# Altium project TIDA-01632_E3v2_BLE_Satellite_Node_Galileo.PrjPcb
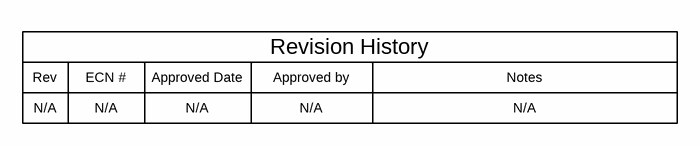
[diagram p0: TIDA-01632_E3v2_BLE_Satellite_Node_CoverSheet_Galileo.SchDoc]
CopyrightYear: 2017; PCB_Layout: Donovan Porter; PCB_Rev: E3; PRJ_Customer: Public Release; PRJ_Engineer: Donovan Porter; PRJ_Number: TIDA-01632; PRJ_Title: TIDA-01632 BLE Car Access Satellite Node Reference Design; SCH_Rev: E3; TechSupport: http://www.ti.com/support; TID: TIDA-01632
3 sheets, 78 parts. Net scope: global (net labels, ports and power ports of the same name join across sheets).
Board file: TIDA-01632_E3v2_BLE_Satellite_Node_Galileo.PcbDoc
Sheets:
  TIDA-01632_E3v2_BLE_Satellite_Node_CoverSheet_Galileo.SchDoc
  TIDA-01632_E3v2_BLE_Satellite_Node_Main_Galileo.SchDoc
  TIDA-01632_E3v2_BLE_Satellite_Node_Hardware_Galileo.SchDoc

## Sheet TIDA-01632_E3v2_BLE_Satellite_Node_CoverSheet_Galileo.SchDoc
size 431 x 279 mm; Date: Not shown in title block; ApprovedBy: Not shown in title block; CheckedBy: Not shown in title block; Author: Not shown in title block; CompanyName: Not shown in title block; Engineer: Not shown in title block; Organization: Not shown in title block; Address1: Not shown in title block; Address2: Not shown in title block; Address3: Not shown in title block; Address4: Not shown in title block; DocumentNumber: 1; Revision: Use project parameter SCH_Rev; SheetNumber: 1; SheetTotal: 3; PageSetup: Record=PageOptions¦CenterHorizontal=True¦CenterVertical=True¦PrintScale=1.00¦XCorrection=1.00¦YCorrection=1.00¦PrintKind=0¦BorderSize=5000000¦LeftOffset=0¦BottomOffset=0¦Orientation=2¦PaperLength=1000¦PaperWidth=1000¦Scale=100¦PaperSource=15¦PrintQuality=600¦MediaType=1¦DitherType=10¦PaperKind=Letter¦PrintScaleMode=1

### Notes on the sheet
- Rev
- N/A
- ECN #
- Approved Date
- Approved by
- Revision History
- Notes

## Sheet TIDA-01632_E3v2_BLE_Satellite_Node_Main_Galileo.SchDoc
size 431 x 279 mm; Date: Not shown in title block; ApprovedBy: Not shown in title block; CheckedBy: Not shown in title block; Author: Not shown in title block; CompanyName: Not shown in title block; Engineer: Not shown in title block; Organization: Not shown in title block; Address1: Not shown in title block; Address2: Not shown in title block; Address3: Not shown in title block; Address4: Not shown in title block; DocumentNumber: 2; Revision: Use project parameter SCH_Rev; SheetNumber: 2; SheetTotal: 3; PageSetup: Record=PageOptions¦CenterHorizontal=True¦CenterVertical=True¦PrintScale=1.00¦XCorrection=1.00¦YCorrection=1.00¦PrintKind=0¦BorderSize=5000000¦LeftOffset=0¦BottomOffset=0¦Orientation=2¦PaperLength=1000¦PaperWidth=1000¦Scale=100¦PaperSource=15¦PrintQuality=600¦MediaType=1¦DitherType=10¦PaperKind=Letter¦PrintScaleMode=1
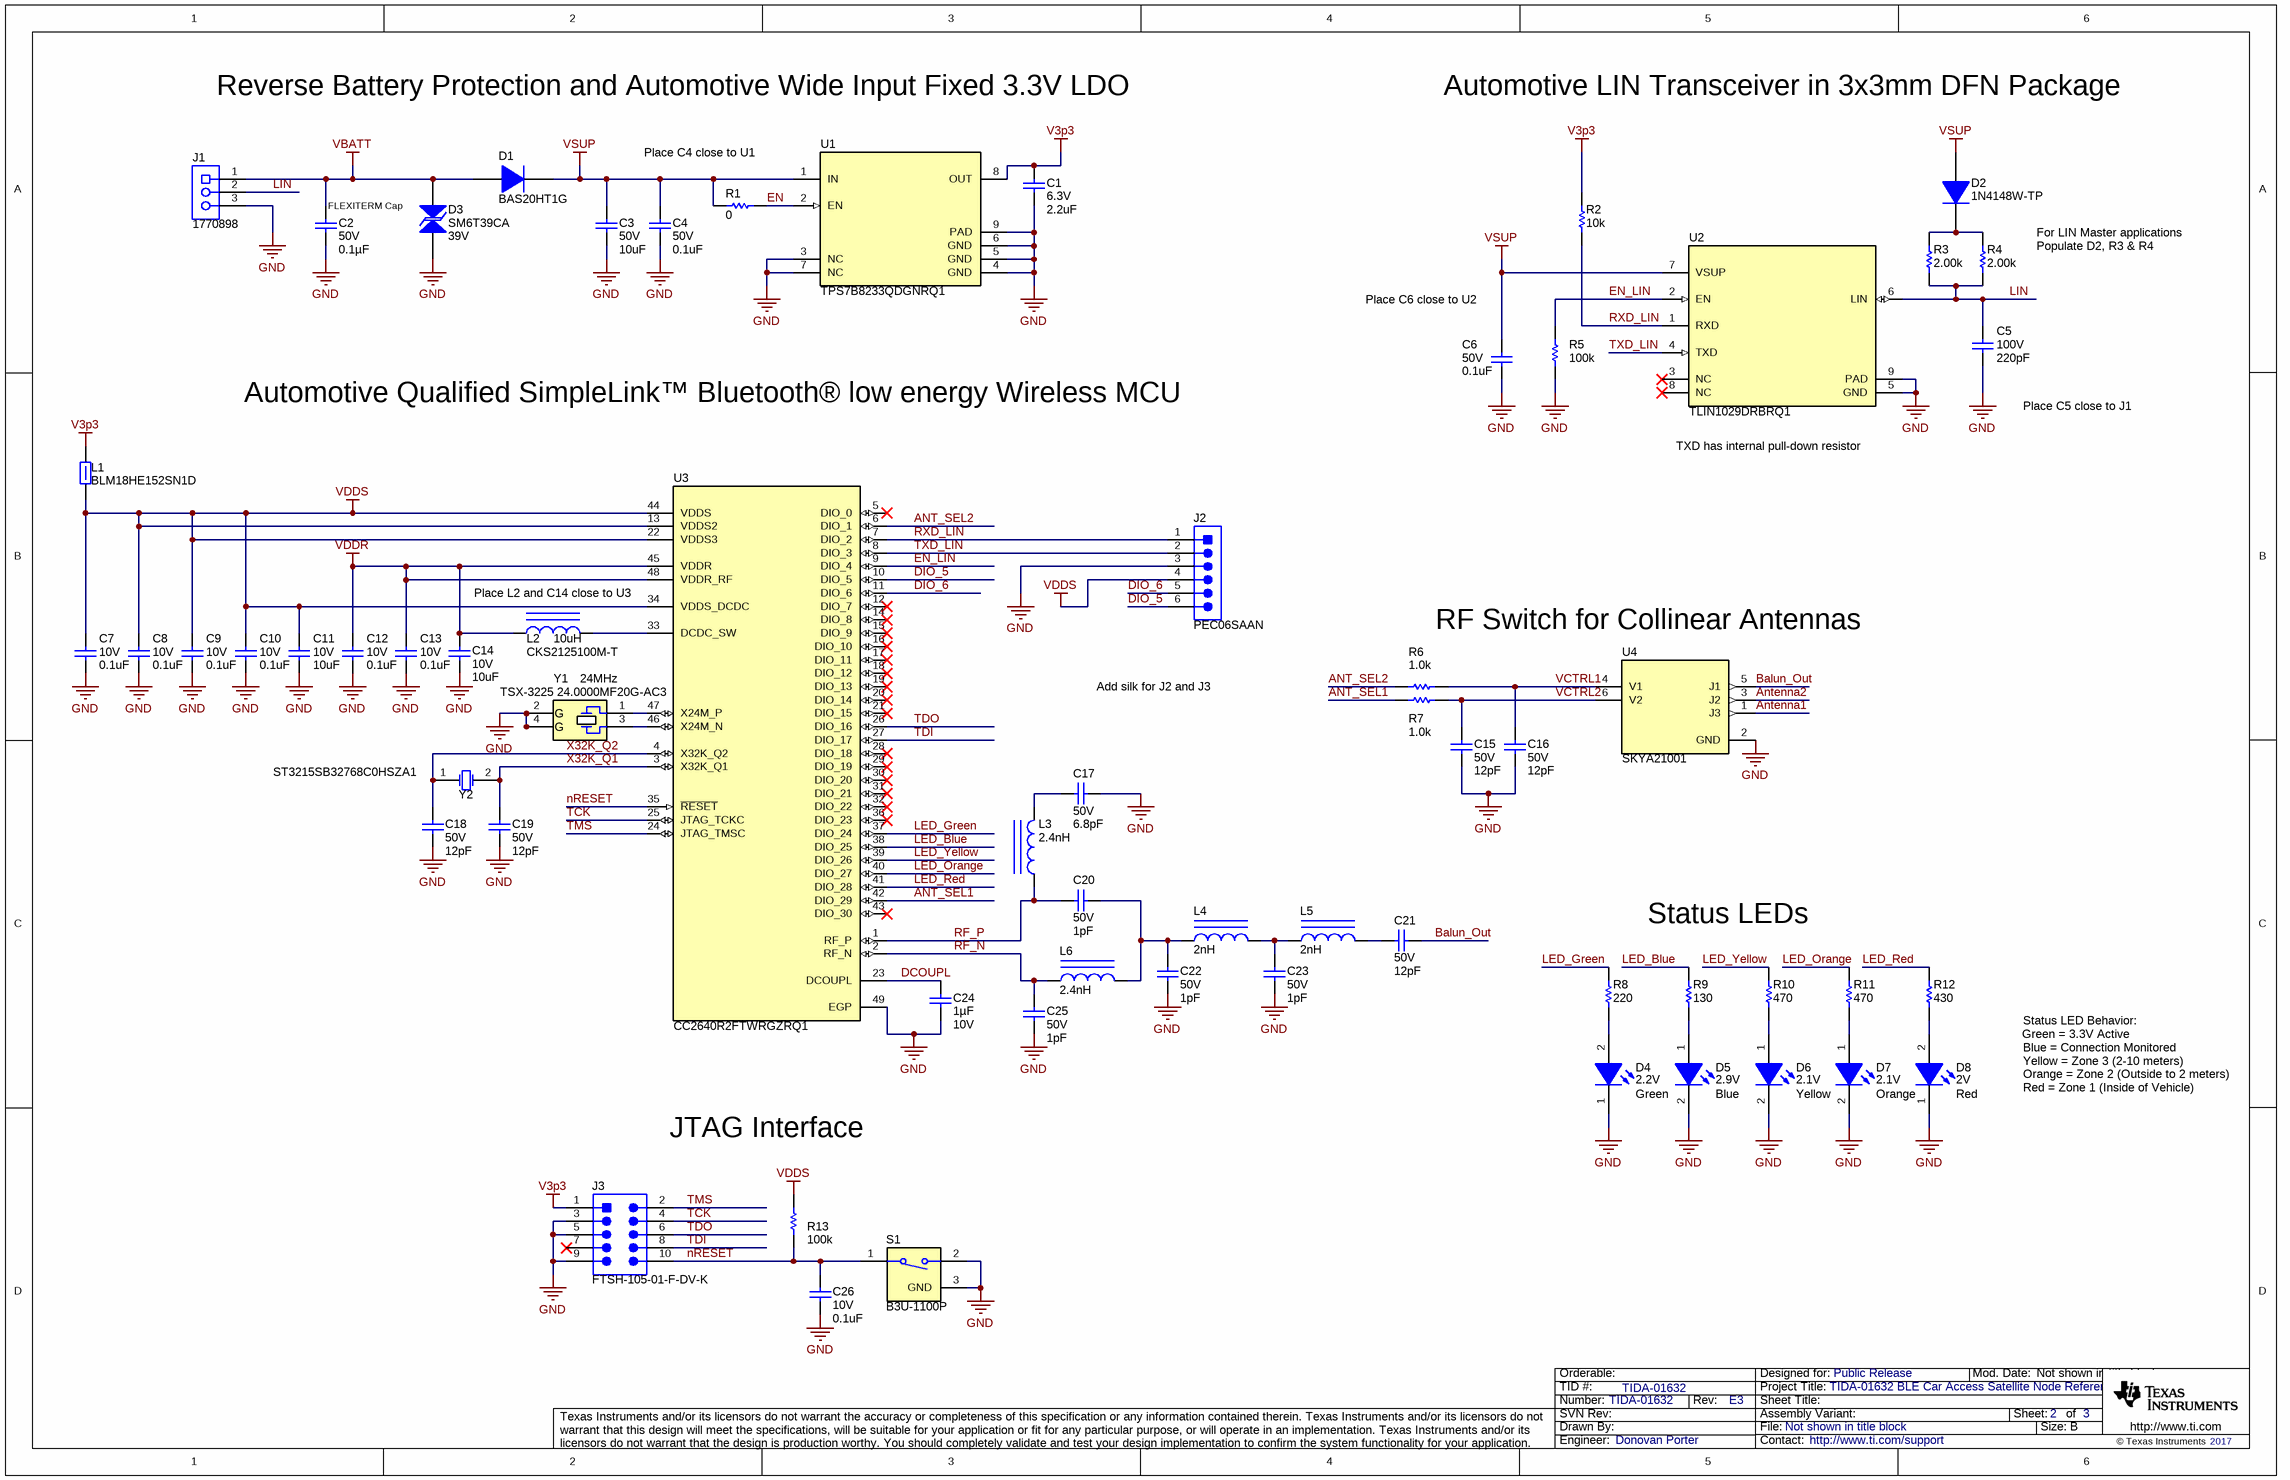
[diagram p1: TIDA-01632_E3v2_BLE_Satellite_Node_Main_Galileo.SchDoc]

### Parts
C1  VDC_V: 6.3V  ValueDisplayed: 2.2uF  [0603]  (hidden comment: GCM188R70J225KE22D)
C2  VDC_V: 50V  ValueDisplayed: 0.1µF  [0603]  (hidden comment: 06035C104KAZ2A)
C3  VDC_V: 50V  ValueDisplayed: 10uF  [1210_280]  (hidden comment: UMK325AB7106KMHT)
C4  VDC_V: 50V  ValueDisplayed: 0.1uF  [0402]  (hidden comment: GCM155R71H104KE02D)
C5  VDC_V: 100V  ValueDisplayed: 220pF  [0402]  (hidden comment: GRM155R72A221KA01D)
C6  VDC_V: 50V  ValueDisplayed: 0.1uF  [0402]  (hidden comment: GCM155R71H104KE02D)
C7  VDC_V: 10V  ValueDisplayed: 0.1uF  [0402L]  (hidden comment: CL05B104KP5NNNC)
C8  VDC_V: 10V  ValueDisplayed: 0.1uF  [0402]  (hidden comment: CL05B104KP5NNNC)
C9  VDC_V: 10V  ValueDisplayed: 0.1uF  [0402]  (hidden comment: CL05B104KP5NNNC)
C10  VDC_V: 10V  ValueDisplayed: 0.1uF  [0402]  (hidden comment: CL05B104KP5NNNC)
C11  VDC_V: 10V  ValueDisplayed: 10uF  [0603]  (hidden comment: GRM188Z71A106MA73D)
C12  VDC_V: 10V  ValueDisplayed: 0.1uF  [0402L]  (hidden comment: CL05B104KP5NNNC)
C13  VDC_V: 10V  ValueDisplayed: 0.1uF  [0402L]  (hidden comment: CL05B104KP5NNNC)
C14  VDC_V: 10V  ValueDisplayed: 10uF  [0603]  (hidden comment: GRM188Z71A106MA73D)
C15  VDC_V: 50V  ValueDisplayed: 12pF  [0402L]  (hidden comment: GRM1555C1H120JA01D)
C16  VDC_V: 50V  ValueDisplayed: 12pF  [0402L]  (hidden comment: GRM1555C1H120JA01D)
C17  VDC_V: 50V  ValueDisplayed: 6.8pF  [0402]  (hidden comment: GRM1555C1H6R8CA01D)
C18  VDC_V: 50V  ValueDisplayed: 12pF  [0402]  (hidden comment: GRM1555C1H120JA01D)
C19  VDC_V: 50V  ValueDisplayed: 12pF  [0402]  (hidden comment: GRM1555C1H120JA01D)
C20  VDC_V: 50V  ValueDisplayed: 1pF  [0402]  (hidden comment: GRM1555C1H1R0CA01D)
C21  VDC_V: 50V  ValueDisplayed: 12pF  [0402L]  (hidden comment: GRM1555C1H120JA01D)
C22  VDC_V: 50V  ValueDisplayed: 1pF  [0402]  (hidden comment: GRM1555C1H1R0CA01D)
C23  VDC_V: 50V  ValueDisplayed: 1pF  [0402L]  (hidden comment: GRM1555C1H1R0CA01D)
C24  Cap_F: 1µF  VDC_V: 10V  [0603L]  (hidden comment: GRM188R71A105KA61D)
C25  VDC_V: 50V  ValueDisplayed: 1pF  [0402]  (hidden comment: GRM1555C1H1R0CA01D)
C26  VDC_V: 10V  ValueDisplayed: 0.1uF  [0402]  (hidden comment: CL05B104KP5NNNC)
D1  BAS20HT1G  [SOD-323]
D2  1N4148W-TP  [SOD-123]
D3  SM6T39CA  value 39V  [SMB-Bi]
D4  value Green  Vf_V: 2.2V  [SML-P1_GREEN]  (hidden comment: SML-P12PTT86)
D5  value Blue  Vf_V: 2.9V  [LED_SMLP12_BLUE]  (hidden comment: SMLP12BC7TT86)
D6  value Yellow  Vf_V: 2.1V  [LED_SMLP12_YELLOW]  (hidden comment: SML-P12YTT86)
D7  value Orange  Vf_V: 2.1V  [LED_SMLP12_ORANGE]  (hidden comment: SML-P12DTT86)
D8  value Red  Vf_V: 2V  [SML-P1_RED]  (hidden comment: SML-P12VTT86)
J1  1770898  [Phoenix_1770898]
J2  PEC06SAAN  [Sullins_PEC06SAAN]
J3  FTSH-105-01-F-DV-K  [Samtec_FTSH-105-01-x-DV-K]
L1  BLM18HE152SN1D  [0603]
L2  ValueDisplayed: 10uH  [0805_HV]  (hidden comment: CKS2125100M-T)
L3  ValueDisplayed: 2.4nH  [IND_LQG15H]  (hidden comment: LQG15HS2N4S02D)
L4  ValueDisplayed: 2nH  [IND_LQG15H]  (hidden comment: LQG15HS2N0S02D)
L5  ValueDisplayed: 2nH  [IND_LQG15H]  (hidden comment: LQG15HS2N0S02D)
L6  ValueDisplayed: 2.4nH  [IND_LQG15H]  (hidden comment: LQG15HS2N4S02D)
R1  ValueDisplayed: 0  [0402]  (hidden comment: CRCW04020000Z0ED)
R2  ValueDisplayed: 10k  [0402]  (hidden comment: CRCW040210K0JNED)
R3  ValueDisplayed: 2.00k  [1206]  (hidden comment: RC1206FR-072KL)
R4  ValueDisplayed: 2.00k  [1206]  (hidden comment: RC1206FR-072KL)
R5  ValueDisplayed: 100k  [0402]  (hidden comment: ERJ-2GEJ104X)
R6  ValueDisplayed: 1.0k  [0603]  (hidden comment: CRCW06031K00JNEA)
R7  ValueDisplayed: 1.0k  [0603]  (hidden comment: CRCW06031K00JNEA)
R8  ValueDisplayed: 220  [0402]  (hidden comment: CRCW0402220RJNED)
R9  ValueDisplayed: 130  [0402]  (hidden comment: CRCW0402130RJNED)
R10  ValueDisplayed: 470  [0402]  (hidden comment: CRCW0402470RJNED)
R11  ValueDisplayed: 470  [0402]  (hidden comment: CRCW0402470RJNED)
R12  ValueDisplayed: 430  [0402]  (hidden comment: CRCW0402430RJNED)
R13  ValueDisplayed: 100k  [0402]  (hidden comment: ERJ-2GEJ104X)
S1  B3U-1100P  [SW_B3U-1100P]
U1  TPS7B8233QDGNRQ1  [DGN0008D_N]
U2  TLIN1029DRBRQ1  [DRB0008F]
U3  CC2640R2FTWRGZRQ1  [RGZ0048N]
U4  SKYA21001  [SOT-363]
Y1  Frequency_Fixed: 24MHz  [EPSON_TSX-3225]  (hidden comment: TSX-3225 24.0000MF20G-AC3)
Y2  ST3215SB32768C0HSZA1  [Kyocera_ST3215SB]

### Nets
GND: C1.2 C2.2 C3.1 C4.2 C5.2 C6.2 C7.2 C8.2 C9.2 C10.2 C11.2 C12.2 C13.2 C14.2 C15.2 C16.2 C17.2 C18.2 C19.2 C22.2 C23.2 C24.2 C25.2 C26.2 D3.1 D4.1(K) D5.2(K) D6.2(K) D7.2(K) D8.1(K) J1.3 J2.3 J3.3 J3.5 J3.9 R5.1 S1.2 S1.3(GND) U1.3(NC) U1.4(GND) U1.5(GND) U1.6(GND) U1.7(NC) U1.9(PAD) U2.5(GND) U2.9(PAD) U3.49(EGP) U4.2(GND) Y1.2(GND) Y1.4(GND)
V3p3: C1.1 J3.1 L1.2 R2.2 U1.8(OUT)
VBATT: C2.1 D1.2(A) D3.2 J1.1
VDDR: C12.1 C13.1 C14.1 L2.2 U3.45(VDDR) U3.48(VDDR_RF)
VDDS: C7.1 C8.1 C9.1 C10.1 C11.1 J2.4 L1.1 R13.2 U3.13(VDDS2) U3.22(VDDS3) U3.34(VDDS_DCDC) U3.44(VDDS)
VSUP: C3.2 C4.1 C6.1 D1.1(K) D2.2(A) R1.1 U1.1(IN) U2.7(VSUP)
ANT_SEL1: R7.1 U3.42(DIO_29)
ANT_SEL2: R6.1 U3.6(DIO_1)
Antenna1: U4.1(J3)
Antenna2: U4.3(J2)
Balun_Out: C21.1 U4.5(J1)
DCOUPL: C24.1 U3.23(DCOUPL)
DIO_5: J2.6 U3.10(DIO_5)
DIO_6: J2.5 U3.11(DIO_6)
EN: R1.2 U1.2(EN)
EN_LIN: R5.2 U2.2(EN) U3.9(DIO_4)
LED_Blue: R9.2 U3.38(DIO_25)
LED_Green: R8.2 U3.37(DIO_24)
LED_Orange: R11.2 U3.40(DIO_27)
LED_Red: R12.2 U3.41(DIO_28)
LED_Yellow: R10.2 U3.39(DIO_26)
LIN: C5.1 J1.2 R3.1 R4.1 U2.6(LIN)
nRESET: C26.1 J3.10 R13.1 S1.1 U3.35(~{RESET})
RF_N: C25.1 L6.1 U3.2(RF_N)
RF_P: C20.2 L3.1 U3.1(RF_P)
RXD_LIN: J2.1 R2.1 U2.1(RXD) U3.7(DIO_2)
TCK: J3.4 U3.25(JTAG_TCKC)
TDI: J3.8 U3.27(DIO_17)
TDO: J3.6 U3.26(DIO_16)
TMS: J3.2 U3.24(JTAG_TMSC)
TXD_LIN: J2.2 U2.4(TXD) U3.8(DIO_3)
VCTRL1: C16.1 R6.2 U4.4(V1)
VCTRL2: C15.1 R7.2 U4.6(V2)
X32K_Q1: C19.1 U3.3(X32K_Q1) Y2.2(OSC2)
X32K_Q2: C18.1 U3.4(X32K_Q2) Y2.1(OSC1)
NetC17_1: C17.1 L3.2
NetC20_1: C20.1 C22.1 L4.1 L6.2
NetC21_2: C21.2 L5.2
NetC23_1: C23.1 L4.2 L5.1
NetD2_1: D2.1(K) R3.2 R4.2
NetD4_2: D4.2(A) R8.1
NetD5_1: D5.1(A) R9.1
NetD6_1: D6.1(A) R10.1
NetD7_1: D7.1(A) R11.1
NetD8_2: D8.2(A) R12.1
NetL2_1: L2.1 U3.33(DCDC_SW)
NetU3_46: U3.46(X24M_N) Y1.3
NetU3_47: U3.47(X24M_P) Y1.1

Not connected (* = marked no-connect by the designer): J3 7*; U2 3(NC)* 8(NC)*; U3 5(DIO_0)* 12(DIO_7)* 14(DIO_8)* 15(DIO_9)* 16(DIO_10)* 17(DIO_11)* 18(DIO_12)* 19(DIO_13)* 20(DIO_14)* 21(DIO_15)* 28(DIO_18)* 29(DIO_19)* 30(DIO_20)* 31(DIO_21)* 32(DIO_22)* 36(DIO_23)* 43(DIO_30)*

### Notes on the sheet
- Reverse Battery Protection and Automotive Wide Input Fixed 3.3V LDO
- Automotive LIN Transceiver in 3x3mm DFN Package
- Place C4 close to U1
- (near C2) FLEXITERM Cap
- For LIN Master applications
- (near C6) Place C6 close to U2
- Populate D2, R3 & R4
- Automotive Qualified SimpleLink™ Bluetooth® low energy Wireless MCU
- Place C5 close to J1
- (near U2) TXD has internal pull-down resistor
- Place L2 and C14 close to U3
- RF Switch for Collinear Antennas
- Add silk for J2 and J3
- Status LEDs
- Status LED Behavior:
- Green = 3.3V Active
- Yellow = Zone 3 (2-10 meters)
- Blue = Connection Monitored
- Orange = Zone 2 (Outside to 2 meters)
- Red = Zone 1 (Inside of Vehicle)
- JTAG Interface

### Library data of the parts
C1 = CMP-0007134-5: CAP, CERM, 2.2 uF, 6.3 V, +/- 10%, X7R, AEC-Q200 Grade 1, 0603; Manufacturer: MuRata; TaMin_C: -55°C; Polarized: N; SizeAreaWB_mm2: 4.68; Value1: Unknown; U/M: EA; Value: 2.2uF; TaMax_C: 125°C; SizeZ_mm: 1; SizeX_mm: 1.6; SizeY_mm: 0.8; SizeArea_mm2: 1.28; CompType: Capacitor; AEC Qualified: Y; Cap_F: 2.2µF; AEC Category: Q200
C2 = CMP-0079095-1: CAP, CERM, 0.1 µF, 50 V,+/- 10%, X7R, AEC-Q200 Grade 1, 0603; Manufacturer: AVX; Cap_F: 100nF; SizeAreaWB_mm2: 4.68; SizeArea_mm2: 1.28; AEC Qualified: Y; AEC Category: Q200; Value: 0.1uF; TaMax_C: 125°C; SizeZ_mm: 1; Polarized: N; TaMin_C: -55°C; SizeY_mm: 0.8; U/M: EA; SizeX_mm: 1.6
C3 = CMP-0009258-2: CAP, CERM, 10 uF, 50 V, +/- 10%, X7R, AEC-Q200 Grade 1, 1210; Manufacturer: Taiyo Yuden; TaMin_C: -55°C; Polarized: N; SizeAreaWB_mm2: 14.7; Value1: Unknown; U/M: EA; Value: 10uF; TaMax_C: 125°C; SizeZ_mm: 2.8; SizeX_mm: 3.2; SizeY_mm: 2.5; Cap_Case: 1210; SizeArea_mm2: 8; CompType: Capacitor; AEC Qualified: Y; Cap_F: 10µF; AEC Grade: 1; AEC Category: Q200
C4 C6 = CMP-0006356-2: CAP, CERM, 0.1 uF, 50 V, +/- 10%, X7R, AEC-Q200 Grade 1, 0402; Manufacturer: MuRata; TaMin_C: -55°C; Polarized: N; SizeAreaWB_mm2: 3; Value1: Unknown; U/M: EA; Value: 0.1uF; TaMax_C: 125°C; SizeZ_mm: 0.6; SizeX_mm: 1; SizeY_mm: 0.5; CompType: Capacitor; AEC Qualified: Y; Cap_F: 100nF; AEC Category: Q200
C5 = CMP-0006703-2: CAP, CERM, 220 pF, 100 V, +/- 10%, X7R, 0402; Manufacturer: MuRata; TaMin_C: -55°C; Polarized: N; SizeAreaWB_mm2: 3; Value1: Unknown; U/M: EA; Value: 220pF; TaMax_C: 125°C; SizeZ_mm: 0.6; SizeX_mm: 1; SizeY_mm: 0.5; CompType: Capacitor; AEC Category: Q200
C7 C12 C13 = CMP-0006343-2: CAP, CERM, 0.1 uF, 10 V, +/- 10%, X7R, 0402; Manufacturer: Samsung Electro-Mechanics; TaMin_C: -55°C; Polarized: N; SizeAreaWB_mm2: 3; Value1: Unknown; U/M: EA; Value: 0.1uF; TaMax_C: 125°C; SizeZ_mm: 0.6; SizeX_mm: 1; SizeY_mm: 0.5; Cap_Case: 0402; CompType: Capacitor; Cap_F: 100nF; AEC Category: Q200
C8-C10 C26 = CMP-0006343-2: CAP, CERM, 0.1 uF, 10 V, +/- 10%, X7R, 0402; Manufacturer: Samsung Electro-Mechanics; TaMin_C: -55°C; Polarized: N; SizeAreaWB_mm2: 3; Value1: Unknown; U/M: EA; Value: 0.1uF; TaMax_C: 125°C; SizeZ_mm: 0.6; SizeX_mm: 1; SizeY_mm: 0.5; Cap_F: 100nF; AEC Category: Q200
C11 C14 = CMP-0007497-5: CAP, CERM, 10 uF, 10 V, +/- 20%, X7R, 0603; Manufacturer: MuRata; TaMin_C: -55°C; Polarized: N; SizeAreaWB_mm2: 4.68; Value1: Unknown; U/M: EA; Value: 10uF; TaMax_C: 125°C; SizeZ_mm: 1; SizeX_mm: 1.6; SizeY_mm: 0.8; SizeArea_mm2: 1.28; Cap_F: 10µF; AEC Category: Q200
C15 C16 C21 = CMP-0006415-2: CAP, CERM, 12 pF, 50 V, +/- 5%, C0G/NP0, 0402; Manufacturer: MuRata; TaMin_C: -55°C; Polarized: N; SizeAreaWB_mm2: 3; Value1: Unknown; U/M: EA; Value: 12pF; TaMax_C: 125°C; SizeZ_mm: 0.6; SizeX_mm: 1; SizeY_mm: 0.5; Cap_Case: 0402; CompType: Capacitor; AEC Category: Q200
C17 = CMP-0006488-2: CAP, CERM, 6.8 pF, 50 V, +/- 5%, C0G/NP0, 0402; Manufacturer: MuRata; TaMin_C: -55°C; Polarized: N; SizeAreaWB_mm2: 3; Value1: Unknown; U/M: EA; Value: 6.8pF; TaMax_C: 125°C; SizeZ_mm: 0.6; SizeX_mm: 1; SizeY_mm: 0.5; AEC Category: Q200
C18 C19 = CMP-0006415-2: CAP, CERM, 12 pF, 50 V, +/- 5%, C0G/NP0, 0402; Manufacturer: MuRata; TaMin_C: -55°C; Polarized: N; SizeAreaWB_mm2: 3; Value1: Unknown; U/M: EA; Value: 12pF; TaMax_C: 125°C; SizeZ_mm: 0.6; SizeX_mm: 1; SizeY_mm: 0.5; CompType: Capacitor; AEC Category: Q200
C20 C22 C25 = CMP-0006427-2: CAP, CERM, 1 pF, 50 V, +/- 5%, C0G/NP0, 0402; Manufacturer: MuRata; TaMin_C: -55°C; Polarized: N; SizeAreaWB_mm2: 3; Value1: Unknown; U/M: EA; Value: 1pF; TaMax_C: 125°C; SizeZ_mm: 0.6; SizeX_mm: 1; SizeY_mm: 0.5; AEC Category: Q200
C23 = CMP-0006427-2: CAP, CERM, 1 pF, 50 V, +/- 5%, C0G/NP0, 0402; Manufacturer: MuRata; TaMin_C: -55°C; Polarized: N; SizeAreaWB_mm2: 3; Value1: Unknown; U/M: EA; Value: 1pF; TaMax_C: 125°C; SizeZ_mm: 0.6; SizeX_mm: 1; SizeY_mm: 0.5; Cap_Case: 0402; CompType: Capacitor; AEC Category: Q200
C24 = CMP-0007365-4: CAP, CERM, 1 uF, 10 V, +/- 10%, X7R, 0603; Manufacturer: MuRata; TaMin_C: -55°C; ESR_ohm: 0.011; Polarized: N; SizeAreaWB_mm2: 4.68; Value1: 0.011 ohm; U/M: EA; Value: 1uF; TaMax_C: 125°C; SizeZ_mm: 1; SizeX_mm: 1.6; SizeY_mm: 0.8; Cap_Case: 0603; SizeArea_mm2: 1.28; AEC Category: Q200
D1 = CMP-0029150-1: Diode, Switching, 200 V, 0.2 A, AEC-Q101, SOD-323; Manufacturer: ON Semiconductor; Io_A: 2dA; Green_Lifecycle: Not Set; SizeAreaWB_mm2: 8.695; Vr_V: 200V; Green_REACh: Incomplete; Value1: 0.2A; TJmax_C: 150°C; U/M: EA; Value: 200V; SizeZ_mm: 1; SizeX_mm: 2.7; SizeY_mm: 1.35; Vf_V: 1.25V; SizeArea_mm2: 3.645; AEC Qualified: Y; AEC Category: Q101
D2 = CMP-0076974-1: Diode, Switching, 100 V, 0.15 A, SOD-123; Manufacturer: Micro Commercial Components; SizeAreaWB_mm2: 13.095; Vr_V: 100V; SizeArea_mm2: 6.545; TJmax_C: 150°C; AEC Category: Q101; Value: 100V; SizeZ_mm: 1.35; Green_REACh: Incomplete; Io_A: 1.5dA; Vf_V: 1.25V; SizeY_mm: 1.7; Green_Lifecycle: Not Set; U/M: EA; Value1: 0.15A; SizeX_mm: 3.85
D3 = CMP-0006050-2: Diode, TVS, Bi, 39 V, SMB; Manufacturer: STMicroelectronics; Value1: W; RJA_CperW: 100; U/M: EA; AEC Category: Q101
D4 = CMP-0002873-1: LED, Green, SMD; Manufacturer: Rohm; Io_A: 20mA; Value1: W; U/M: EA; Type: AlInGaP
D5 = CMP-0002838-1: LED, Blue, SMD; Manufacturer: Rohm; Io_A: 5mA; Tjmax_C: 85°C; Value1: W; U/M: EA; Type: InGaN
D6 = CMP-0002839-1: LED, Yellow, SMD; Manufacturer: Rohm; Io_A: 20mA; Tjmax_C: 85°C; Value1: W; U/M: EA; Type: InGaN
D7 = CMP-0002841-1: LED, Orange, SMD; Manufacturer: Rohm; Io_A: 20mA; Tjmax_C: 85°C; Value1: W; U/M: EA; Type: InGaN
D8 = CMP-0003003-2: LED, Red, SMD; Manufacturer: Rohm; Io_A: 20mA; Power_TotalModule: 50mW; Vr_V: 5V; Tjmax_C: 85°C; Value1: 0.05W; U/M: EA; Ir_A: 10µA; Type: AlInGaP; RJC_CperW: 643
J1 = CMP-0084507-1: Terminal Block, 3 Pos, 2.5mm, R/A, TH; Manufacturer: Phoenix Contact; Gender: Female; Cert_VDE: Y; Pitch_mm: 2.5; Voltage_V: 160V; Row_Count: 1; Current_A: 6A
J2 = CMP-0054567-1: Header, 100mil, 6x1, Tin, TH; Manufacturer: Sullins Connector Solutions; CNHeader: TRUE; Green_Lifecycle: Not Set; Green_REACh: Incomplete; CT: FALSE
J3 = CMP-0075670-2: Header (Shrouded), 1.27mm, 5x2, Gold, SMT; Manufacturer: Samtec; Pitch_mm: 1.27; Gender: Male; Cert_CSA: Y; Current_A: 3.3A; Row_Count: 2
L1 = CMP-0003349-2: Ferrite Bead, 1500 ohm @ 100 MHz, 0.5 A, 0603; Manufacturer: MuRata; Ztyp@1GHz_Ohm: 1.5k; SizeAreaWB_mm2: 4.68; DCR_ohm: 5d; Value1: 0.5 ohm; Imax_A: 5dA; SizeZ_mm: 1; SizeX_mm: 1.6; SizeY_mm: 0.8; Value2: 0.5A; SizeArea_mm2: 1.28
L2 = CMP-0059606-1: Inductor, Multilayer, Ferrite, 10 uH, 0.11 A, 0.52 ohm, SMD; Manufacturer: Taiyo Yuden; Green_Lifecycle: Active; SizeAreaWB_mm2: 6.75; DCR_ohm: 5.2d; Green_REACh: Passed; Value: 10uH; Imax_A: 1.1dA; SizeZ_mm: 1.45; SizeX_mm: 2; SizeY_mm: 1.25; Value2: 0.11A; SizeArea_mm2: 2.5; Ind_H: 10µH; AEC Category: Q200
L3 L6 = CMP-0058626-1: Inductor, Multilayer, Air Core, 2.4 nH, 0.3 A, 0.15 ohm, SMD; Manufacturer: MuRata; Isat: 0.3A @ % inductance drop; Irms: 0.3A @ C rise; Green_Lifecycle: Active; SizeAreaWB_mm2: 3; DCR_ohm: 1.5d; Green_REACh: Passed; Value: 2.4nH; Imax_A: 3dA; SizeZ_mm: 0.55; SizeX_mm: 1; SizeY_mm: 0.5; Value2: 0.3A; AEC Category: Q200
L4 L5 = CMP-0058624-1: Inductor, Multilayer, Air Core, 2 nH, 0.3 A, 0.1 ohm, SMD; Manufacturer: MuRata; Isat: 0.3A @ % inductance drop; Irms: 0.3A @ C rise; Green_Lifecycle: Active; SizeAreaWB_mm2: 3; DCR_ohm: 1d; Green_REACh: Passed; Value1: 0.1 ohm; Value: 2nH; Imax_A: 3dA; SizeZ_mm: 0.55; SizeX_mm: 1; SizeY_mm: 0.5; Value2: 0.3A; AEC Category: Q200
R1 = CMP-0026822-3: RES, 0, 5%, 0.063 W, AEC-Q200 Grade 0, 0402; Manufacturer: Vishay-Dale; Power_W: 63mW; TempCo: 200 ppm/C; Value_Code: 0000; Value: 0; EIA_Code: E24; SizeX_mm: 1; SizeY_mm: 0.5; SizeZ_mm: 0.6; Value2: 0.063W; AEC Qualified: Y; VDC_V: 50V; AEC Category: Q200
R2 = CMP-0026825-5: RES, 10 k, 5%, 0.063 W, AEC-Q200 Grade 0, 0402; Manufacturer: Vishay-Dale; Power_W: 63mW; TempCo: 200 ppm/C; Value_Code: 10k0; Value: 10k; EIA_Code: E24; SizeX_mm: 1; SizeY_mm: 0.5; SizeZ_mm: 0.6; Value2: 0.063W; CompType: Resistor; AEC Qualified: Y; VDC_V: 50V; AEC Category: Q200; AEC Grade: 0
R3 R4 = CMP-0018158-2: RES, 2.00 k, 1%, 0.25 W, 1206; Manufacturer: Yageo America; Power_W: 250mW; TempCo: 100 ppm/C; Value_Code: 2k00; U/M: EA; Value: 2.00k; EIA_Code: E96; Res_ohm: 2k; SizeX_mm: 3.2; SizeY_mm: 1.6; SizeZ_mm: 1.35; Value2: 0.25W; SizeArea_mm2: 5.12; CompType: Resistor; VDC_V: 200V; AEC Category: Q200
R5 R13 = CMP-0026995-2: RES, 100 k, 5%, 0.1 W, AEC-Q200 Grade 0, 0402; Manufacturer: Panasonic; Power_W: 100mW; TempCo: 200 ppm/C; U/M: EA; Value: 100k; EIA_Code: E24; SizeX_mm: 1; SizeY_mm: 0.5; SizeZ_mm: 0.6; Value2: 0.1W; CompType: Resistor; AEC Qualified: Y; VDC_V: 50V; AEC Grade: 0; AEC Category: Q200
R6 R7 = CMP-0025729-4: RES, 1.0 k, 5%, 0.1 W, AEC-Q200 Grade 0, 0603; Manufacturer: Vishay-Dale; Power_W: 100mW; TempCo: 200 ppm/C; Value_Code: 1k00; Value: 1.0k; EIA_Code: E24; Res_ohm: 1k; SizeX_mm: 1.6; SizeY_mm: 0.8; SizeZ_mm: 1; Value2: 0.1W; SizeArea_mm2: 1.28; AEC Qualified: Y; VDC_V: 75V; AEC Category: Q200; AEC Grade: 0
R8 = CMP-0026878-3: RES, 220, 5%, 0.063 W, AEC-Q200 Grade 0, 0402; Manufacturer: Vishay-Dale; Power_W: 63mW; TempCo: 200 ppm/C; Value_Code: 220R; Value: 220; EIA_Code: E24; SizeX_mm: 1; SizeY_mm: 0.5; SizeZ_mm: 0.6; Value2: 0.063W; AEC Qualified: Y; VDC_V: 50V; AEC Category: Q200; AEC Grade: 0
R9 = CMP-0026837-3: RES, 130, 5%, 0.063 W, AEC-Q200 Grade 0, 0402; Manufacturer: Vishay-Dale; Power_W: 63mW; TempCo: 200 ppm/C; Value_Code: 130R; Value: 130; EIA_Code: E24; SizeX_mm: 1; SizeY_mm: 0.5; SizeZ_mm: 0.6; Value2: 0.063W; AEC Qualified: Y; VDC_V: 50V; AEC Category: Q200; AEC Grade: 0
R10 R11 = CMP-0026934-3: RES, 470, 5%, 0.063 W, AEC-Q200 Grade 0, 0402; Manufacturer: Vishay-Dale; Power_W: 63mW; TempCo: 200 ppm/C; Value_Code: 470R; Value: 470; EIA_Code: E24; SizeX_mm: 1; SizeY_mm: 0.5; SizeZ_mm: 0.6; Value2: 0.063W; AEC Qualified: Y; VDC_V: 50V; AEC Category: Q200; AEC Grade: 0
R12 = CMP-0026930-3: RES, 430, 5%, 0.063 W, AEC-Q200 Grade 0, 0402; Manufacturer: Vishay-Dale; Power_W: 63mW; TempCo: 200 ppm/C; Value_Code: 430R; Value: 430; EIA_Code: E24; SizeX_mm: 1; SizeY_mm: 0.5; SizeZ_mm: 0.6; Value2: 0.063W; AEC Qualified: Y; VDC_V: 50V; AEC Category: Q200; AEC Grade: 0
S1 = CMP-0002193-2: Switch, SPST-NO, Off-Mom, 12 V, SMD; Manufacturer: Omron Electronic Components; CurrentRating_mA: 50A; PositionCount: 1; VDC_V: 12V
U1 = CMP-0013312-4: 300mA High-Voltage Ultra-Low-Iq Low-Dropout (LDO) Regulator, DGN0008D (VSSOP-8); Manufacturer: Texas Instruments; SizeX_mm: 5.05; SizeY_mm: 3.1; CompType: IC; SizeZ_mm: 1.1; SizeArea_mm2: 15.655; SizeAreaWB_mm2: 35.955; AEC Category: Q200; AEC Qualified: Y
U2 = CMP-0079115-1: Local Interconnect Network (LIN) Transceiver with Dominant State Timeout, DRB0008F (VSON-8); Alternate PartNumber: TLIN1029DRBTQ1; Alternate Manufacturer: Texas Instruments; SizeAreaWB_mm2: 16; SizeZ_mm: 1; SizeX_mm: 3; SizeArea_mm2: 9; CompType: IC; AEC Qualified: Y; AEC Category: Q200
U3 = CMP-0079117-1: Automotive Qualified SimpleLink Bluetooth low energy Wireless MCU, RGZ0048N (VQFN-48); Alternate PartNumber: CC2640R2FTWRGZTQ1; Alternate Manufacturer: Texas Instruments; SizeAreaWB_mm2: 81; SizeZ_mm: 1; SizeX_mm: 7; SizeArea_mm2: 49; CompType: IC; AEC Qualified: Y; AEC Category: Q200
U4 = CMP-0084444-1: 20 MHz to 3.0 GHz SPDT Switch, SOT-363; Manufacturer: Skyworks Solutions; SizeZ_mm: 1.1; SizeX_mm: 2.2; SizeAreaWB_mm2: 10.24; SizeArea_mm2: 4.84
Y1 = CMP-0004609-3: Crystal, 24 MHz, 9 pF, SMD; Manufacturer: Epson; TaMin_C: -40°C; Frequency Stability: +/-20ppm; TaMax_C: 85°C
Y2 = CMP-0079334-1: Crystal, 32.768 KHz, 20 ppm, SMD; Manufacturer: Kyocera; SizeAreaWB_mm2: 10.5; SizeArea_mm2: 4.8; Frequency Tolerance: 20 ppm; AEC Category: Q200; TaMax_C: 85°C; SizeZ_mm: 0.9; TaMin_C: -40°C; SizeY_mm: 1.5; SizeX_mm: 3.2

## Sheet TIDA-01632_E3v2_BLE_Satellite_Node_Hardware_Galileo.SchDoc
size 431 x 279 mm; Date: Not shown in title block; ApprovedBy: Not shown in title block; CheckedBy: Not shown in title block; Author: Not shown in title block; CompanyName: Not shown in title block; Engineer: Not shown in title block; Organization: Not shown in title block; Address1: Not shown in title block; Address2: Not shown in title block; Address3: Not shown in title block; Address4: Not shown in title block; DocumentNumber: 3; Revision: Use project parameter SCH_Rev; SheetNumber: 3; SheetTotal: 3; PageSetup: Record=PageOptions¦CenterHorizontal=True¦CenterVertical=True¦PrintScale=1.00¦XCorrection=1.00¦YCorrection=1.00¦PrintKind=0¦BorderSize=5000000¦LeftOffset=0¦BottomOffset=0¦Orientation=2¦PaperLength=1000¦PaperWidth=1000¦Scale=100¦PaperSource=15¦PrintQuality=600¦MediaType=1¦DitherType=10¦PaperKind=Letter¦PrintScaleMode=1
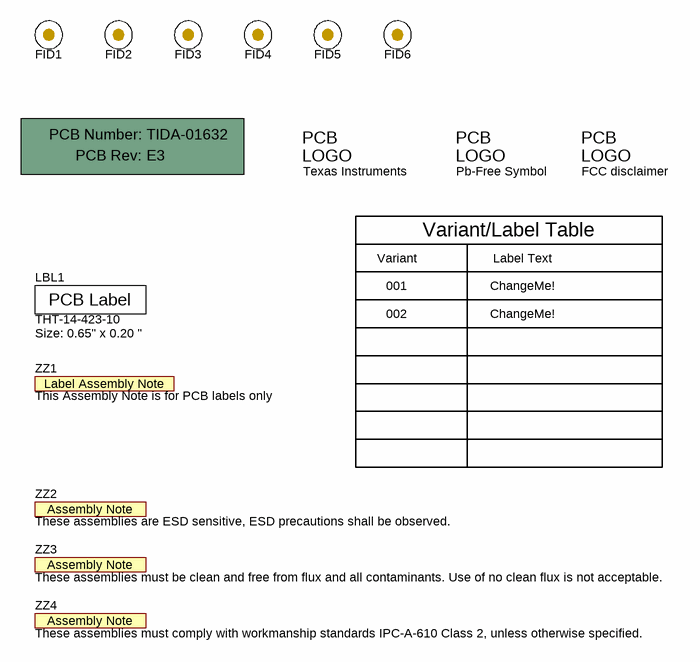
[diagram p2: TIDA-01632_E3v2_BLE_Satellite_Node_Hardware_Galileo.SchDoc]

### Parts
!PCB1  Printed Circuit Board  (value not drawn)  (mechanical)
FID1  Fiducial  [Fiducial10-20]  (value not drawn)
FID2  Fiducial  [Fiducial10-20]  (value not drawn)
FID3  Fiducial  [Fiducial10-20]  (value not drawn)
FID4  Fiducial  [Fiducial10-20]  (value not drawn)
FID5  Fiducial  [Fiducial10-20]  (value not drawn)
FID6  Fiducial  [Fiducial10-20]  (value not drawn)
LBL1  THT-14-423-10  Note: Size: 0.65" x 0.20 "  [Label_650x200]
Logo1  Texas Instruments  [TI_Stacked_Overlay_Small]  (no BOM)
Logo2  Pb-Free Symbol  [Pb-Free_Overlay_Small]  (no BOM)
Logo3  FCC disclaimer  [FCC_disclaimer]  (no BOM)
ZZ1  This Assembly Note is for PCB labels only  [AssemblyNoteLabel]  (no BOM)
ZZ2  These assemblies are ESD sensitive, ESD precautions shall be observed.  [AssemblyNote]  (no BOM)
ZZ3  These assemblies must be clean and free from flux and all contaminants. Use of no clean flux is not acceptable.  [AssemblyNote]  (no BOM)
ZZ4  These assemblies must comply with workmanship standards IPC-A-610 Class 2, unless otherwise specified.  [AssemblyNote]  (no BOM)

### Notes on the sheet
- Variant/Label Table
- Variant
- 001
- Label Text
- ChangeMe!
- 002

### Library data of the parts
!PCB1 = CMP-0003618-2: Manufacturer: Any; PartNumber: TIDA-01632; CompType: PCB
FID1-FID6 = CMP-0077181-1: Fiducial mark.  There is nothing to buy or mount.
LBL1 = CMP-0003625-1: Thermal Transfer Printable Labels, 0.650" W x 0.200" H - 10,000 per roll; Manufacturer: Brady; CompType: Label
Logo1 = CMP-0074838-1: Texas Instrument Corporate Signature; SymbolCreator: a0412235; Lib Reference: TI_Logo; Library Reference: Logo
Logo2 = CMP-0074839-1: SymbolCreator: a0412235; Library Reference: Logo
Logo3 = CMP-0074847-1: FCC_disclaimer; Library Reference: Logo
ZZ1 = CMP-0003616-3
ZZ2 = CMP-0077236-1
ZZ3 = CMP-0077237-1
ZZ4 = CMP-0077238-1

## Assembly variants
001: not fitted C23 D2 FID1 FID2 FID3 FID4 FID5 FID6 R3 R4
